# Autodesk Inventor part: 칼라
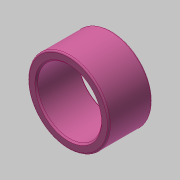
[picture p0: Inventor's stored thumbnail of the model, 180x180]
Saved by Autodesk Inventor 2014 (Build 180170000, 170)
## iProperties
Created: 2019-05
Part Number: 칼라
Material: 스테인리스강
Document SubType Name: Modeling
Designer: mduedu
Density: 1 g/cm^3
Appearance: 분홍색
Author: mduedu
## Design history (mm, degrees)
sketch "스케치1"
  geometry: C1 r 11 at (0, 0); C2 r 14 at (0, 0); 1 further point
  constraints: 2 centre point, 2 coincident
  dimensions: "d0" = 22 diameter of C1; "d1" = 28 diameter of C2
extrude "돌출1" new body sketch "스케치1" distance "d2" = 15; taper "d3" = 0 deg
fillet "모깎기1" dims "d4" = 0.5
chamfer "모따기1" distance "d5" = 0.5; stored, may be unused: second distance "d6" = 2, angle "d7" = 45 deg
node "솔리드1"
